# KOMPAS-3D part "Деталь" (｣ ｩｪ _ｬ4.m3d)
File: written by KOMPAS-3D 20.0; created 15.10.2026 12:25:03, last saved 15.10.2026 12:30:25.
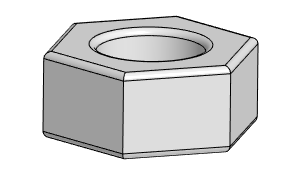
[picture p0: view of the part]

Document properties: Полное имя файла: D:\RicWork\Project-EPS32\box_compas\прочее\гайка_м4.m3d

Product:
- Part/product: Деталь
    Масса: 0.000743087

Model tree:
1. Эскиз:1
2. Элемент выдавливания:1
     Расстояние 1 = 3.2
3. Скругление:1  (with: Элемент выдавливания:1)
     Радиус = 0.25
